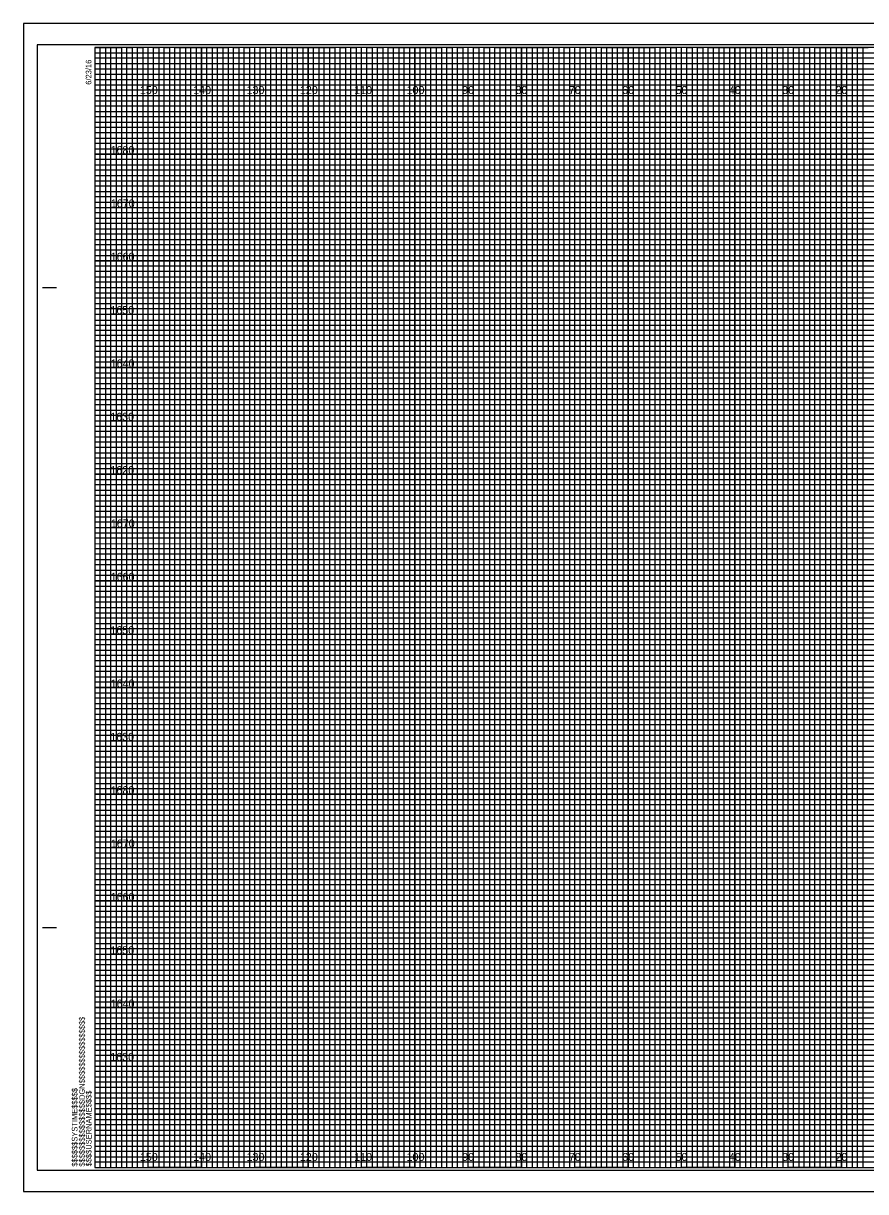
# Model space of a CAD drawing. Extents: x -13 to 323, y -5 to 2414.
# Drawn here: x -13.4 to 144.5, y 875.5 to 1094.5 of the extents above; entities that cross this region are included whole.
import ezdxf

# ---------------------------------------------------------------- set-up
doc = ezdxf.new("R2010")
doc.units = 0
for name, color, linetype in [('Prop XS Elevation Labels', 7, 'Continuous'), ('Prop XS Offset Labels', 7, 'Continuous'), ('Sheet Cross Section CELL', 7, 'Continuous'), ('Sheet Cross Section Grid Major CELL', 7, 'Continuous'), ('Sheet Cross Section Grid Middle CELL', 7, 'Continuous'), ('Sheet Cross Section Grid Minor 1 CELL', 7, 'Continuous'), ('Sheet Cross Section Grid Minor 2 CELL', 7, 'Continuous'), ('Sheet Cutting Line CELL', 7, 'Continuous'), ('Sheet DOT Grid CELL', 7, 'Continuous'), ('Sheet Plot Border Inside CELL', 7, 'Continuous'), ('Sheet Plot Border Outside CELL', 7, 'Continuous')]:
    doc.layers.add(name, color=color, linetype=linetype)

msp = doc.modelspace()

# ---------------------------------------------------------------- linework, layer by layer
at = {"layer": 'Sheet Cross Section CELL'}
for p, q in [((-9.8, 1045), (-7.3, 1045)), ((-9.7, 1045), (-7.2, 1045)), ((-9.8, 925), (-7.3, 925)), ((-9.7, 925), (-7.2, 925)), ((0, 880), (0, 880)), ((0, 880), (0, 880)), ((0, 880), (0, 880)), ((0, 880), (0, 880)), ((0, 880), (0, 880)), ((0, 880), (0, 880)), ((0, 880), (0, 880))]:
    msp.add_line(p, q, dxfattribs=at)
msp.add_lwpolyline([(320, 1090), (0, 1090), (0, 880), (320, 880)], close=True, dxfattribs=at)
at = {"layer": 'Sheet Cross Section Grid Major CELL'}
for p, q in [((10, 1090), (0, 1090)), ((10, 880), (10, 1090)), ((30, 1090), (20, 1090)), ((20, 1090), (20, 880)), ((30, 880), (30, 1090)), ((50, 1090), (40, 1090)), ((40, 1090), (40, 880)), ((50, 880), (50, 1090)), ((70, 1090), (60, 1090)), ((60, 1090), (60, 880)), ((70, 880), (70, 1090)), ((90, 1090), (80, 1090)), ((80, 1090), (80, 880)), ((90, 880), (90, 1090)), ((110, 1090), (100, 1090)), ((100, 1090), (100, 880)), ((110, 880), (110, 1090)), ((130, 1090), (120, 1090)), ((120, 1090), (120, 880)), ((130, 880), (130, 1090)), ((150, 1090), (140, 1090)), ((140, 1090), (140, 880)), ((20, 880), (10, 880)), ((40, 880), (30, 880)), ((60, 880), (50, 880)), ((80, 880), (70, 880)), ((100, 880), (90, 880)), ((120, 880), (110, 880)), ((140, 880), (130, 880))]:
    msp.add_line(p, q, dxfattribs=at)
for points in [[(0, 1080), (320, 1080), (320, 1070), (0, 1070)], [(0, 1060), (320, 1060), (320, 1050), (0, 1050)], [(0, 1040), (320, 1040), (320, 1030), (0, 1030)], [(0, 1020), (320, 1020), (320, 1010), (0, 1010)], [(0, 1000), (320, 1000), (320, 990), (0, 990)], [(0, 980), (320, 980), (320, 970), (0, 970)], [(0, 960), (320, 960), (320, 950), (0, 950)], [(0, 940), (320, 940), (320, 930), (0, 930)], [(0, 920), (320, 920), (320, 910), (0, 910)], [(0, 900), (320, 900), (320, 890), (0, 890)]]:
    msp.add_lwpolyline(points, dxfattribs=at)
at = {"layer": 'Sheet Cross Section Grid Middle CELL'}
for points in [[(0, 1090), (5, 1090), (5, 880), (15, 880), (15, 1090), (25, 1090), (25, 880), (35, 880), (35, 1090), (45, 1090), (45, 880), (55, 880), (55, 1090), (65, 1090), (65, 880), (75, 880), (75, 1090), (85, 1090), (85, 880), (95, 880), (95, 1090), (105, 1090), (105, 880), (115, 880), (115, 1090), (125, 1090), (125, 880), (135, 880), (135, 1090), (145, 1090)], [(0, 1085), (275, 1085)], [(0, 1065), (320, 1065), (320, 1075), (0, 1075)], [(0, 1045), (320, 1045), (320, 1055), (0, 1055)], [(0, 1025), (320, 1025), (320, 1035), (0, 1035)], [(0, 1005), (320, 1005), (320, 1015), (0, 1015)], [(0, 985), (320, 985), (320, 995), (0, 995)], [(0, 965), (320, 965), (320, 975), (0, 975)], [(0, 945), (320, 945), (320, 955), (0, 955)], [(0, 925), (320, 925), (320, 935), (0, 935)], [(0, 905), (320, 905), (320, 915), (0, 915)], [(0, 885), (320, 885), (320, 895), (0, 895)]]:
    msp.add_lwpolyline(points, dxfattribs=at)
at = {"layer": 'Sheet Cross Section Grid Minor 1 CELL'}
for p, q in [((0, 1089), (260, 1089)), ((260, 1087.98), (0, 1087.98)), ((0, 1087.98), (0, 1087)), ((0, 1087), (260, 1087)), ((260, 1085.89), (0, 1085.89)), ((0, 1085.89), (0, 1084)), ((0, 1084), (320, 1084))]:
    msp.add_line(p, q, dxfattribs=at)
for points in [[(0, 1083), (270, 1083), (320, 1083), (320, 1082), (0, 1082)], [(0, 1081), (320, 1081), (320, 1079), (0, 1079)], [(0, 1078), (320, 1078), (320, 1077), (0, 1076.98)], [(0, 1076), (320, 1076), (320, 1074), (0, 1074)], [(0, 1073), (320, 1073), (320, 1072), (0, 1072)], [(0, 1071), (320, 1071), (320, 1069), (0, 1069)], [(0, 1068), (320, 1068), (320, 1067), (0, 1067)], [(0, 1066), (320, 1066), (320, 1064), (0, 1064)], [(0, 1063), (320, 1063), (320, 1062), (0, 1062)], [(0, 1061), (320, 1061), (320, 1059), (0, 1059)], [(0, 1058), (320, 1058), (320, 1057), (0, 1057)], [(0, 1056), (320, 1056), (320, 1053.95), (320, 1053), (320, 1052), (0, 1052)], [(0, 1054), (320, 1054), (320, 1053), (0, 1053)], [(0, 1051), (320, 1051), (320, 1049), (0, 1049.03)], [(0, 1049.03), (320, 1049), (320, 1048), (0, 1048)], [(0, 1047), (320, 1047), (320, 1046), (0, 1046)], [(0, 1044), (320, 1044), (320, 1043), (0, 1043)], [(0, 1042), (320, 1042), (320, 1041), (0, 1041)], [(-0.07, 1038.89), (320, 1038.89), (320, 1037.88), (-0.07, 1037.88)], [(0, 1037), (320, 1037), (320, 1036), (0, 1036)], [(0, 1034), (320, 1034), (320, 1033), (0, 1033)], [(0, 1032), (320, 1032), (320, 1031), (0, 1031)], [(0, 1029), (320, 1029), (320, 1028), (0, 1028)], [(0, 1027), (320, 1027), (320, 1026), (0, 1026)], [(0, 1024), (320, 1024), (320, 1023), (0, 1023)], [(0, 1022), (320, 1022), (320, 1021), (0, 1021)], [(0, 1019), (320, 1019), (319.99, 1017.98), (0, 1018)], [(0, 1017), (320, 1017), (320, 1016), (0, 1016)], [(0, 1014), (320, 1014), (320, 1013), (0, 1013)], [(0, 1012), (320, 1012), (320, 1011), (0, 1011)], [(0, 1009), (320, 1009), (320, 1008), (0, 1008)], [(0, 1007), (320, 1007), (320, 1006), (0, 1006)], [(0, 1004), (320, 1004), (320, 1003), (0, 1003)], [(0, 1002), (320, 1002), (320, 1001), (0, 1001)], [(0, 999), (320, 999), (320, 998), (0, 998)], [(0, 996.99), (320.07, 996.91), (320, 996), (0, 996)], [(0, 994), (320, 994), (320, 993), (0, 993)], [(0, 992), (320, 992), (320, 991), (0, 991)], [(0, 989), (320, 989), (320, 988), (0, 988)], [(0, 987), (320, 987), (320, 986), (0, 986)], [(0, 984), (320, 984), (320, 983), (0, 983)], [(0, 982), (320, 982), (320, 981), (0, 981)], [(0, 979), (320, 979), (320, 978), (0, 978)], [(0, 977), (320, 977), (320, 976), (0, 976)], [(0, 974), (320, 974), (320, 973), (0, 973)], [(0, 972), (320, 972), (320, 971), (0, 971)], [(0, 969), (320, 969), (320, 968), (0, 968)], [(0, 967), (320, 967), (320, 966), (0, 966)], [(0, 964), (320, 964), (320, 963), (0, 963)], [(0, 962), (320, 962), (320, 961), (0, 961)], [(0, 959), (320, 959), (319.99, 957.98), (0, 958)], [(0, 957), (320, 957), (320, 956), (0, 956)], [(0, 954), (320, 954), (320, 953), (0, 953)], [(0, 952), (320, 952), (320, 951), (0, 951)], [(0, 949), (320, 949), (320, 948), (0, 948)], [(0, 947), (320, 947), (320, 946), (0, 946)], [(0, 944), (320, 944), (320, 943), (0, 943)], [(0, 942), (320, 942), (320, 941), (0, 941)], [(0, 939), (320, 939), (320, 938), (0, 938)], [(0, 936.99), (320.07, 936.91), (320, 936), (0, 936)], [(0, 934), (320, 934), (320, 933), (0, 933)], [(0, 932), (320, 932), (320, 931), (0, 931)], [(0, 929), (320, 929), (320, 928), (0, 928)], [(0, 927), (320, 927), (320, 926), (0, 926)], [(0, 924), (320, 924), (320, 923), (0, 923)], [(0, 922), (320, 922), (320, 921), (0, 921)], [(0, 919), (320, 919), (320, 918), (0, 918)], [(0, 917), (320, 917), (320, 916), (0, 916)], [(0, 914), (320, 914), (320, 913), (0, 913)], [(0, 912), (320, 912), (320, 911), (0, 911)], [(0, 909), (320, 909), (320, 908), (0, 908)], [(0, 907), (320, 907), (320, 906), (0, 906)], [(0, 904), (320, 904), (320, 903), (0, 903)], [(0, 902), (320, 902), (320, 901), (0, 901)], [(0, 899), (320, 899), (320, 898), (0, 898)], [(0, 897), (320, 897), (320, 896), (0, 896)], [(0, 894), (320, 894), (320, 893), (0, 893)], [(0, 892), (320, 892), (320, 891), (0, 891)], [(0, 889), (320, 889), (320, 888), (0, 888)], [(0, 887), (320, 887), (320, 886), (0, 886)], [(0, 884), (320, 884), (320, 883), (0, 883)], [(0, 882), (320, 882), (320, 881), (0, 881)]]:
    msp.add_lwpolyline(points, dxfattribs=at)
at = {"layer": 'Sheet Cross Section Grid Minor 2 CELL'}
for points in [[(0, 880), (1, 880), (1, 1090), (2, 1090), (2, 880)], [(2, 880), (3, 880), (3, 1090), (4, 1090), (4, 880)], [(5, 880), (6, 880), (6, 1090), (7, 1090), (7, 880)], [(7, 880), (8, 880), (8, 1090), (9, 1090), (9, 880)], [(10, 880), (11, 880), (11, 1090), (12, 1090), (12, 880)], [(12, 880), (13, 880), (13, 1090), (14, 1090), (14, 880)], [(15, 880), (16, 880), (16, 1090), (17, 1090), (17, 880)], [(17, 880), (18, 880), (18, 1090), (19, 1090), (19, 880)], [(20, 880), (21, 880), (21, 1090), (22, 1090), (22, 880)], [(22, 880), (23, 880), (23, 1090), (24, 1090), (24, 880)], [(25, 880), (26, 880), (26, 1090), (27, 1090), (27, 880)], [(27, 880), (28, 880), (28, 1090), (29, 1090), (29, 880)], [(30, 880), (31, 880), (31, 1090), (32, 1090), (32, 880)], [(32, 880), (33, 880), (33, 1090), (34, 1090), (34, 880)], [(35, 880), (36, 880), (36, 1090), (37, 1090), (37, 880)], [(37, 880), (38, 880), (38, 1090), (39, 1090), (39, 880)], [(40, 880), (41, 880), (41, 1090), (42, 1090), (42, 880)], [(42, 880), (43, 880), (43, 1090), (44, 1090), (44, 880)], [(45, 880), (46, 880), (46, 1090), (47, 1090), (47, 880)], [(47, 880), (48, 880), (48, 1090), (49, 1090), (49, 880)], [(50, 880), (51, 880), (51, 1090), (52, 1090), (52, 880)], [(52, 880), (53, 880), (53, 1090), (54, 1090), (54, 880)], [(55, 880), (56, 880), (56, 1090), (57, 1090), (57, 880)], [(57, 880), (58, 880), (58, 1090), (59, 1090), (59, 880)], [(60, 880), (61, 880), (61, 1090), (62, 1090), (62, 880)], [(62, 880), (63, 880), (63, 1090), (64, 1090), (64, 880)], [(65, 880), (66, 880), (66, 1090), (67, 1090), (67, 880)], [(67, 880), (68, 880), (68, 1090), (69, 1090), (69, 880)], [(70, 880), (71, 880), (71, 1090), (72, 1090), (72, 880)], [(72, 880), (73, 880), (73, 1090), (74, 1090), (74, 880)], [(75, 880), (76, 880), (76, 1090), (77, 1090), (77, 880)], [(77, 880), (78, 880), (78, 1090), (79, 1090), (79, 880)], [(80, 880), (81, 880), (81, 1090), (82, 1090), (82, 880)], [(82, 880), (83, 880), (83, 1090), (84, 1090), (84, 880)], [(85, 880), (86, 880), (86, 1090), (87, 1090), (87, 880)], [(87, 880), (88, 880), (88, 1090), (89, 1090), (89, 880)], [(90, 880), (91, 880), (91, 1090), (92, 1090), (92, 880)], [(92, 880), (93, 880), (93, 1090), (94, 1090), (94, 880)], [(95, 880), (96, 880), (96, 1090), (97, 1090), (97, 880)], [(97, 880), (98, 880), (98, 1090), (99, 1090), (99, 880)], [(100, 880), (101, 880), (101, 1090), (102, 1090), (102, 880)], [(102, 880), (103, 880), (103, 1090), (104, 1090), (104, 880)], [(105, 880), (106, 880), (106, 1090), (107, 1090), (107, 880)], [(107, 880), (108, 880), (108, 1090), (109, 1090), (109, 880)], [(110, 880), (111, 880), (111, 1090), (112, 1090), (112, 880)], [(112, 880), (113, 880), (113, 1090), (114, 1090), (114, 880)], [(115, 880), (116, 880), (116, 1090), (117, 1090), (117, 880)], [(117, 880), (118, 880), (118, 1090), (119, 1090), (119, 880)], [(120, 880), (121, 880), (121, 1090), (122, 1090), (122, 880)], [(122, 880), (123, 880), (123, 1090), (124, 1090), (124, 880)], [(125, 880), (126, 880), (126, 1090), (127, 1090), (127, 880)], [(127, 880), (128, 880), (128, 1090), (129, 1090), (129, 880)], [(130, 880), (131, 880), (131, 1090), (132, 1090), (132, 880)], [(132, 880), (133, 880), (133, 1090), (134, 1090), (134, 880)], [(135, 880), (136, 880), (136, 1090), (137, 1090), (137, 880)], [(137, 880), (138, 880), (138, 1090), (139, 1090), (139, 880)], [(140, 880), (141, 880), (141, 1090), (142, 1090), (142, 880)], [(142, 880), (143, 880), (143, 1090), (144, 1090), (144, 880)]]:
    msp.add_lwpolyline(points, dxfattribs=at)
at = {"layer": 'Sheet Cutting Line CELL'}
for p, q in [((323.3, 1094.5), (-13.4, 1094.5)), ((-13.4, 1094.5), (-13.4, 875.5)), ((-13.4, 875.5), (323.3, 875.5))]:
    msp.add_line(p, q, dxfattribs=at)
at = {"layer": 'Sheet DOT Grid CELL'}
for p, q in [((10, 880), (10, 1090)), ((20, 880), (20, 1090)), ((30, 880), (30, 1090)), ((40, 880), (40, 1090)), ((50, 880), (50, 1090)), ((60, 880), (60, 1090)), ((70, 880), (70, 1090)), ((80, 880), (80, 1090)), ((90, 880), (90, 1090)), ((100, 880), (100, 1090)), ((110, 880), (110, 1090)), ((120, 880), (120, 1090)), ((130, 880), (130, 1090)), ((140, 880), (140, 1090)), ((0, 1080), (320, 1080)), ((0, 1070), (320, 1070)), ((0, 1060), (320, 1060)), ((0, 1050), (320, 1050)), ((0, 1040), (320, 1040)), ((0, 1030), (320, 1030)), ((0, 1020), (320, 1020)), ((0, 1010), (320, 1010)), ((0, 1000), (320, 1000)), ((0, 990), (320, 990)), ((0, 980), (320, 980)), ((0, 970), (320, 970)), ((0, 960), (320, 960)), ((0, 950), (320, 950)), ((0, 940), (320, 940)), ((0, 930), (320, 930)), ((0, 920), (320, 920)), ((0, 910), (320, 910)), ((0, 900), (320, 900)), ((0, 890), (320, 890))]:
    msp.add_line(p, q, dxfattribs=at)
at = {"layer": 'Sheet Plot Border Inside CELL'}
msp.add_lwpolyline([(-10.8, 879.5), (322.4, 879.5), (322.4, 1090.5), (-10.8, 1090.5)], close=True, dxfattribs=at)
at = {"layer": 'Sheet Plot Border Outside CELL'}
msp.add_lwpolyline([(-13.4, 875.5), (323.3, 875.5), (323.3, 1094.5), (-13.4, 1094.5)], close=True, dxfattribs=at)

# ---------------------------------------------------------------- texts
at = {"layer": 'Prop XS Elevation Labels'}
for s, p in [('1680', (2.95, 1070)), ('1670', (3, 1060)), ('1660', (2.97, 1050)), ('1650', (2.92, 1040)), ('1640', (2.97, 1030)), ('1630', (2.89, 1020)), ('1620', (2.9, 1010)), ('1670', (3, 1000)), ('1660', (2.97, 990)), ('1650', (2.92, 980)), ('1640', (2.97, 970)), ('1630', (2.89, 960)), ('1680', (2.95, 950)), ('1670', (3, 940)), ('1660', (2.97, 930)), ('1650', (2.92, 920)), ('1640', (2.97, 910)), ('1630', (2.89, 900))]:
    msp.add_text(s, height=1.5, dxfattribs=at).set_placement(p)
at = {"layer": 'Prop XS Offset Labels'}
for s, p in [('150', (8.44, 1081.25)), ('140', (18.44, 1081.25)), ('130', (28.44, 1081.25)), ('120', (38.44, 1081.25)), ('110', (48.62, 1081.25)), ('100', (58.44, 1081.25)), ('90', (68.86, 1081.25)), ('80', (78.86, 1081.25)), ('70', (88.86, 1081.25)), ('60', (98.86, 1081.25)), ('50', (108.86, 1081.25)), ('40', (118.86, 1081.25)), ('30', (128.86, 1081.25)), ('20', (138.86, 1081.25)), ('150', (8.44, 881.25)), ('140', (18.44, 881.25)), ('130', (28.44, 881.25)), ('120', (38.44, 881.25)), ('110', (48.62, 881.25)), ('100', (58.44, 881.25)), ('90', (68.86, 881.25)), ('80', (78.86, 881.25)), ('70', (88.86, 881.25)), ('60', (98.86, 881.25)), ('50', (108.86, 881.25)), ('40', (118.86, 881.25)), ('30', (128.86, 881.25)), ('20', (138.86, 881.25))]:
    msp.add_text(s, height=1.5, dxfattribs=at).set_placement(p)
at = {"layer": 'Sheet Cross Section CELL'}
for s, p in [('6/23/16', (-0.65, 1083)), ('$$$$$$$$$$$$$$$$DGN$$$$$$$$$$$$$$$$', (-1.88, 880.18)), ('$$$$$$SYSTIME$$$$$', (-3.26, 880.18)), ('$$$$USERNAME$$$$', (-0.62, 880.23))]:
    msp.add_text(s, height=1.05, rotation=90, dxfattribs=at).set_placement(p)

doc.saveas('drawing.dxf')
